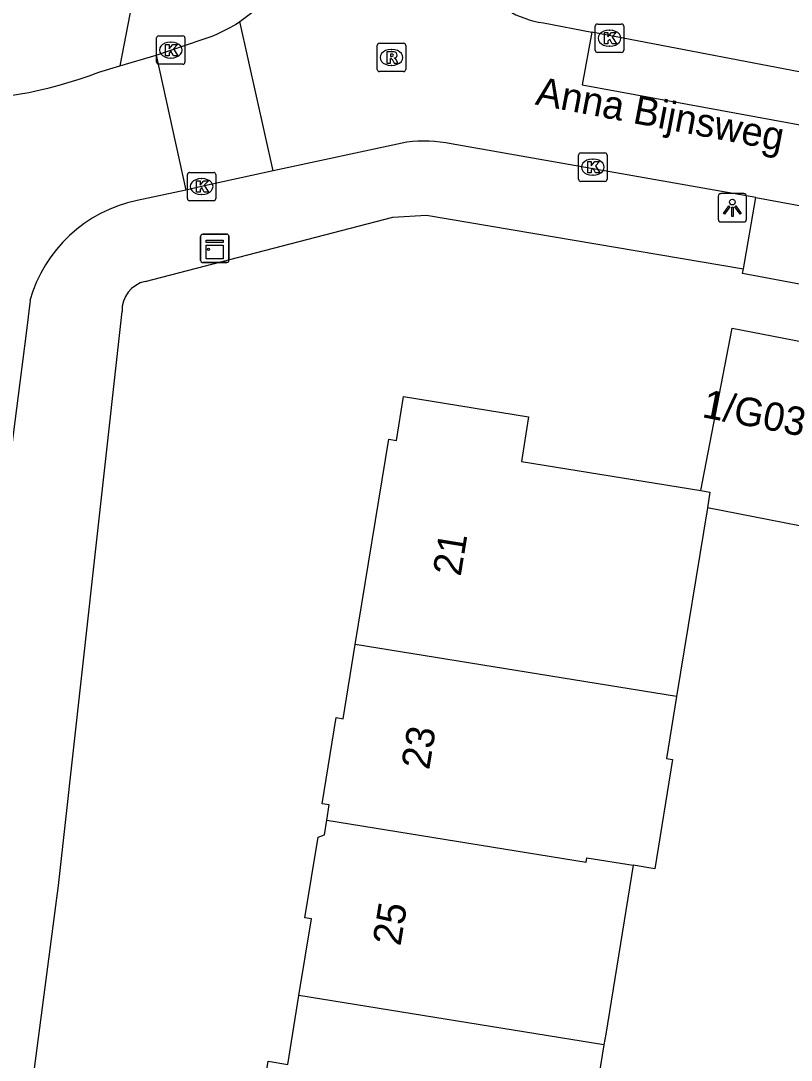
# Model space of a CAD drawing. Extents: x 161402 to 161933, y 381650 to 382313.
# Drawn here: x 161806.73 to 161833.87, y 381916.01 to 381952.64 of the extents above; entities that cross this region are included whole.
import ezdxf

# ---------------------------------------------------------------- set-up
doc = ezdxf.new("R2010")
doc.units = 0
for name, color, linetype in [('IMGEO_Kast', 7, 'Continuous'), ('IMGEO_Kolk', 7, 'Continuous'), ('IMGEO_Lichtpunt', 7, 'Continuous'), ('IMGEO_Openbare_ruimte_label', 7, 'Continuous'), ('IMGEO_Pand', 7, 'Continuous'), ('IMGEO_Pand_nummerreeks', 7, 'Continuous'), ('IMGEO_Rijbaan_lokaal_open', 7, 'Continuous'), ('IMGEO_Rioolput', 7, 'Continuous'), ('IMGEO_Voetpad_open', 7, 'Continuous')]:
    doc.layers.add(name, color=color, linetype=linetype)

msp = doc.modelspace()

# ---------------------------------------------------------------- linework, layer by layer
at = {"layer": 'IMGEO_Kast'}
for p, q in [((161813.066, 381944.199), (161813.066, 381945.04)), ((161813.066, 381945.04), (161813.066, 381944.199)), ((161813.141, 381945.124), (161813.982, 381945.124)), ((161813.982, 381945.124), (161813.141, 381945.124)), ((161814.066, 381945.049), (161814.066, 381944.208)), ((161814.066, 381944.208), (161814.066, 381945.049)), ((161813.991, 381944.124), (161813.15, 381944.124)), ((161813.15, 381944.124), (161813.991, 381944.124))]:
    msp.add_line(p, q, dxfattribs=at)
for points in [[(161813.261, 381944.914), (161813.861, 381944.914), (161813.861, 381944.829), (161813.261, 381944.829), (161813.261, 381944.914)], [(161813.261, 381944.739), (161813.861, 381944.739), (161813.861, 381944.25), (161813.261, 381944.25), (161813.261, 381944.739)]]:
    msp.add_lwpolyline(points, dxfattribs=at)
msp.add_circle((161813.345, 381944.588), 0.0377, dxfattribs=at)
for centre, start, end in [((161813.144, 381945.046), 92.4484, 184.2845), ((161813.144, 381945.046), 92.4484, 184.2845), ((161813.988, 381945.046), 2.4484, 94.2845), ((161813.988, 381945.046), 2.4484, 94.2845), ((161813.144, 381944.202), 182.4484, 274.2845), ((161813.144, 381944.202), 182.4484, 274.2845), ((161813.988, 381944.202), 272.4484, 4.2845), ((161813.988, 381944.202), 272.4484, 4.2845)]:
    msp.add_arc(centre, 0.0779, start, end, dxfattribs=at)
at = {"layer": 'IMGEO_Kolk'}
for p, q in [((161826.973, 381951.603), (161826.973, 381952.455)), ((161827.048, 381952.529), (161827.9, 381952.529)), ((161827.974, 381952.455), (161827.974, 381951.603)), ((161811.516, 381951.184), (161811.516, 381952.036)), ((161811.591, 381952.11), (161812.443, 381952.11)), ((161812.517, 381952.036), (161812.517, 381951.184)), ((161827.461, 381952.309), (161827.486, 381952.309)), ((161812.004, 381951.89), (161812.029, 381951.89)), ((161827.484, 381951.749), (161827.459, 381951.749)), ((161812.027, 381951.33), (161812.002, 381951.33)), ((161827.9, 381951.529), (161827.048, 381951.529)), ((161812.443, 381951.11), (161811.591, 381951.11)), ((161826.459, 381947.984), (161827.311, 381947.984)), ((161826.384, 381947.058), (161826.384, 381947.91)), ((161826.872, 381947.764), (161826.897, 381947.764)), ((161827.385, 381947.91), (161827.385, 381947.058)), ((161812.678, 381947.3), (161813.53, 381947.3)), ((161812.603, 381946.374), (161812.603, 381947.226)), ((161813.091, 381947.08), (161813.116, 381947.08)), ((161813.604, 381947.226), (161813.604, 381946.374)), ((161827.311, 381946.984), (161826.459, 381946.984)), ((161826.895, 381947.204), (161826.87, 381947.204)), ((161813.114, 381946.52), (161813.089, 381946.52)), ((161813.53, 381946.3), (161812.678, 381946.3))]:
    msp.add_line(p, q, dxfattribs=at)
for points in [[(161826.973, 381951.603), (161826.973, 381952.455)], [(161827.048, 381952.529), (161827.9, 381952.529)], [(161827.974, 381952.455), (161827.974, 381951.603)], [(161811.516, 381951.184), (161811.516, 381952.036)], [(161811.591, 381952.11), (161812.443, 381952.11)], [(161812.517, 381952.036), (161812.517, 381951.184)], [(161827.294, 381952.229), (161827.417, 381952.229), (161827.417, 381952.078), (161827.547, 381952.229), (161827.711, 381952.229), (161827.565, 381952.078), (161827.718, 381951.829), (161827.566, 381951.829), (161827.481, 381951.993), (161827.417, 381951.926), (161827.417, 381951.829), (161827.294, 381951.829), (161827.294, 381952.229)], [(161811.837, 381951.81), (161811.96, 381951.81), (161811.96, 381951.659), (161812.09, 381951.81), (161812.254, 381951.81), (161812.108, 381951.659), (161812.261, 381951.41), (161812.109, 381951.41), (161812.024, 381951.574), (161811.96, 381951.507), (161811.96, 381951.41), (161811.837, 381951.41), (161811.837, 381951.81)], [(161827.9, 381951.529), (161827.048, 381951.529)], [(161812.443, 381951.11), (161811.591, 381951.11)], [(161826.459, 381947.984), (161827.311, 381947.984)], [(161826.384, 381947.058), (161826.384, 381947.91)], [(161826.705, 381947.684), (161826.828, 381947.684), (161826.828, 381947.533), (161826.958, 381947.684), (161827.122, 381947.684), (161826.976, 381947.533), (161827.129, 381947.284), (161826.977, 381947.284), (161826.892, 381947.448), (161826.828, 381947.381), (161826.828, 381947.284), (161826.705, 381947.284), (161826.705, 381947.684)], [(161827.385, 381947.91), (161827.385, 381947.058)], [(161812.678, 381947.3), (161813.53, 381947.3)], [(161812.603, 381946.374), (161812.603, 381947.226)], [(161812.924, 381947), (161813.047, 381947), (161813.047, 381946.849), (161813.177, 381947), (161813.341, 381947), (161813.195, 381946.849), (161813.348, 381946.6), (161813.196, 381946.6), (161813.111, 381946.764), (161813.047, 381946.697), (161813.047, 381946.6), (161812.924, 381946.6), (161812.924, 381947)], [(161813.604, 381947.226), (161813.604, 381946.374)], [(161827.311, 381946.984), (161826.459, 381946.984)], [(161813.53, 381946.3), (161812.678, 381946.3)]]:
    msp.add_lwpolyline(points, dxfattribs=at)
for centre, start, end in [((161827.05, 381952.453), 91.552, 178.448), ((161827.05, 381952.453), 91.552, 178.448), ((161827.898, 381952.453), 1.552, 88.448), ((161827.898, 381952.453), 1.552, 88.448), ((161811.593, 381952.034), 91.552, 178.448), ((161811.593, 381952.034), 91.552, 178.448), ((161812.441, 381952.034), 1.552, 88.448), ((161812.441, 381952.034), 1.552, 88.448), ((161827.05, 381951.605), 181.552, 268.448), ((161827.05, 381951.605), 181.552, 268.448), ((161827.898, 381951.605), 271.552, 358.448), ((161827.898, 381951.605), 271.552, 358.448), ((161811.593, 381951.186), 181.552, 268.448), ((161811.593, 381951.186), 181.552, 268.448), ((161812.441, 381951.186), 271.552, 358.448), ((161812.441, 381951.186), 271.552, 358.448), ((161826.461, 381947.908), 91.552, 178.448), ((161826.461, 381947.908), 91.552, 178.448), ((161827.309, 381947.908), 1.552, 88.448), ((161827.309, 381947.908), 1.552, 88.448), ((161812.68, 381947.224), 91.552, 178.448), ((161812.68, 381947.224), 91.552, 178.448), ((161813.528, 381947.224), 1.552, 88.448), ((161813.528, 381947.224), 1.552, 88.448), ((161826.461, 381947.06), 181.552, 268.448), ((161826.461, 381947.06), 181.552, 268.448), ((161827.309, 381947.06), 271.552, 358.448), ((161827.309, 381947.06), 271.552, 358.448), ((161812.68, 381946.376), 181.552, 268.448), ((161812.68, 381946.376), 181.552, 268.448), ((161813.528, 381946.376), 271.552, 358.448), ((161813.528, 381946.376), 271.552, 358.448)]:
    msp.add_arc(centre, 0.0765, start, end, dxfattribs=at)
for centre, major_axis, ratio, start_param, end_param in [((161827.46, 381952.029), (-0.387, 0.002), 0.722429, 4.712389, 7.853982), ((161827.485, 381952.029), (-0.39, 0.002), 0.717154, 1.570796, 4.712389), ((161812.003, 381951.61), (-0.387, 0.002), 0.722429, 4.712389, 7.853982), ((161812.028, 381951.61), (-0.39, 0.002), 0.717154, 1.570796, 4.712389), ((161826.871, 381947.484), (-0.387, 0.002), 0.722429, 4.712389, 7.853982), ((161826.896, 381947.484), (-0.39, 0.002), 0.717154, 1.570796, 4.712389), ((161813.09, 381946.8), (-0.387, 0.002), 0.722429, 4.712389, 7.853982), ((161813.115, 381946.8), (-0.39, 0.002), 0.717154, 1.570796, 4.712389)]:
    msp.add_ellipse(centre, major_axis=major_axis, ratio=ratio, start_param=start_param, end_param=end_param, dxfattribs=at)
at = {"layer": 'IMGEO_Lichtpunt'}
for p, q in [((161832.205, 381946.55), (161831.397, 381946.55)), ((161832.205, 381946.55), (161831.397, 381946.55)), ((161831.303, 381946.455), (161831.303, 381945.648)), ((161831.303, 381946.455), (161831.303, 381945.648)), ((161832.299, 381945.648), (161832.299, 381946.455)), ((161832.299, 381945.648), (161832.299, 381946.455)), ((161831.397, 381945.554), (161832.205, 381945.554)), ((161831.397, 381945.554), (161832.205, 381945.554))]:
    msp.add_line(p, q, dxfattribs=at)
for points in [[(161831.677, 381946.119), (161831.716, 381946.091), (161831.528, 381945.829), (161831.49, 381945.856), (161831.677, 381946.119)], [(161831.779, 381946.071), (161831.826, 381946.071), (161831.826, 381945.749), (161831.779, 381945.749), (161831.779, 381946.071)], [(161831.889, 381946.091), (161831.927, 381946.118), (161832.114, 381945.856), (161832.075, 381945.828), (161831.889, 381946.091)]]:
    msp.add_lwpolyline(points, dxfattribs=at)
msp.add_circle((161831.802, 381946.253), 0.0994, dxfattribs=at)
for centre, start, end in [((161831.397, 381946.455), 90, 180), ((161831.397, 381946.455), 90, 180), ((161832.205, 381946.455), 0, 90), ((161832.205, 381946.455), 0, 90), ((161831.397, 381945.648), 180, 270), ((161831.397, 381945.648), 180, 270), ((161832.205, 381945.648), 270, 0), ((161832.205, 381945.648), 270, 360)]:
    msp.add_arc(centre, 0.0946, start, end, dxfattribs=at)
at = {"layer": 'IMGEO_Pand'}
for points in [[(161830.688, 381936.089), (161831.792, 381941.81), (161835.381, 381941.117)], [(161818.518, 381930.668), (161819.696, 381937.9), (161819.967, 381937.856), (161820.218, 381939.401), (161824.623, 381938.684), (161824.368, 381937.114), (161830.688, 381936.089)], [(161830.688, 381936.089), (161831.012, 381936.036), (161830.921, 381935.476)], [(161830.921, 381935.476), (161829.838, 381928.829)], [(161834.172, 381934.848), (161830.921, 381935.476)], [(161817.512, 381924.476), (161817.599, 381925.01), (161817.348, 381925.05), (161817.842, 381928.084), (161818.091, 381928.043), (161818.518, 381930.668)], [(161829.838, 381928.829), (161818.518, 381930.668)], [(161829.838, 381928.829), (161829.481, 381926.639), (161829.693, 381926.605), (161829.066, 381922.76), (161828.31, 381922.883)], [(161816.533, 381918.296), (161816.972, 381920.99), (161816.741, 381921.028), (161817.204, 381923.872), (161817.428, 381923.957), (161817.512, 381924.476)], [(161817.512, 381924.476), (161826.654, 381922.991), (161826.68, 381923.148), (161828.31, 381922.883)], [(161828.31, 381922.883), (161827.341, 381916.933), (161827.279, 381916.551)], [(161814.828, 381912.15), (161815.451, 381915.973), (161816.136, 381915.861), (161816.533, 381918.296)], [(161827.279, 381916.551), (161816.533, 381918.296)], [(161827.279, 381916.551), (161826.26, 381910.293), (161824.053, 381910.652)]]:
    msp.add_lwpolyline(points, dxfattribs=at)
at = {"layer": 'IMGEO_Rijbaan_lokaal_open'}
for points in [[(161815.628, 381947.352), (161814.45, 381952.615)], [(161825.144, 381952.573), (161826.853, 381952.245)], [(161826.853, 381952.245), (161826.511, 381950.381), (161841.229, 381947.681)], [(161811.499, 381951.427), (161812.017, 381951.61), (161813.12, 381951.985)], [(161810.228, 381951.049), (161811.499, 381951.427)], [(161811.499, 381951.427), (161812.553, 381946.677)], [(161809.488, 381950.828), (161810.228, 381951.049)], [(161820.334, 381948.364), (161815.628, 381947.352)], [(161832.624, 381946.415), (161821.896, 381948.301)], [(161815.628, 381947.352), (161813.104, 381946.8), (161812.553, 381946.677)], [(161812.553, 381946.677), (161810.83, 381946.306)], [(161832.624, 381946.415), (161840.719, 381944.921)], [(161807.058, 381942.789), (161806.923, 381941.638), (161805.889, 381933.665), (161804.496, 381922.134), (161803.877, 381917.126)]]:
    msp.add_lwpolyline(points, dxfattribs=at)
for centre, radius, start, end in [((161810.822, 381957.769), 6.303, 305.142, 347.5685), ((161825.556, 381955.744), 3.198, 166.2409, 262.5929), ((161811.723, 381956.654), 4.873, 286.6617, 304.0306), ((161803.949, 381965.532), 15.713, 247.8699, 290.64), ((161820.924, 381943.604), 4.796, 78.3111, 97.0695), ((161811.844, 381941.437), 4.974, 101.7679, 164.2249)]:
    msp.add_arc(centre, radius, start, end, dxfattribs=at)
at = {"layer": 'IMGEO_Rioolput'}
for p, q in [((161819.292, 381950.925), (161819.292, 381951.777)), ((161819.367, 381951.851), (161820.219, 381951.851)), ((161819.78, 381951.631), (161819.805, 381951.631)), ((161820.293, 381951.777), (161820.293, 381950.925)), ((161819.803, 381951.071), (161819.778, 381951.071)), ((161820.219, 381950.851), (161819.367, 381950.851))]:
    msp.add_line(p, q, dxfattribs=at)
for points in [[(161819.292, 381950.925), (161819.292, 381951.777)], [(161819.367, 381951.851), (161820.219, 381951.851)], [(161820.293, 381951.777), (161820.293, 381950.925)], [(161819.881, 381951.549), (161819.629, 381951.551), (161819.629, 381951.151)], [(161819.629, 381951.151), (161819.753, 381951.151), (161819.753, 381951.313), (161819.764, 381951.313)], [(161819.807, 381951.47), (161819.753, 381951.47), (161819.753, 381951.389)], [(161819.753, 381951.389), (161819.805, 381951.389)], [(161819.811, 381951.284), (161819.882, 381951.151), (161820.022, 381951.151), (161819.957, 381951.277)], [(161820.219, 381950.851), (161819.367, 381950.851)]]:
    msp.add_lwpolyline(points, dxfattribs=at)
for centre, radius, start, end in [((161819.369, 381951.775), 0.0765, 91.552, 178.448), ((161819.369, 381951.775), 0.0765, 91.552, 178.448), ((161820.217, 381951.775), 0.0765, 1.552, 88.448), ((161820.217, 381951.775), 0.0765, 1.552, 88.448), ((161819.763, 381951.26), 0.0533, 26.0293, 88.6989), ((161819.789, 381951.578), 0.19, 274.7715, 282.9687), ((161819.813, 381951.374), 0.0964, 77.0061, 93.1865), ((161819.827, 381951.431), 0.0378, 276.6634, 79.6772), ((161819.88, 381951.439), 0.109, 350.3612, 89.416), ((161819.878, 381951.439), 0.112, 277.5842, 350.9817), ((161819.862, 381951.224), 0.108, 29.5134, 73.7905), ((161819.369, 381950.927), 0.0765, 181.552, 268.448), ((161819.369, 381950.927), 0.0765, 181.552, 268.448), ((161820.217, 381950.927), 0.0765, 271.552, 358.448), ((161820.217, 381950.927), 0.0765, 271.552, 358.448)]:
    msp.add_arc(centre, radius, start, end, dxfattribs=at)
for centre, major_axis, ratio, start_param, end_param in [((161819.779, 381951.351), (-0.387, 0.002), 0.722429, 4.712389, 7.853982), ((161819.804, 381951.351), (-0.39, 0.002), 0.717154, 1.570796, 4.712389)]:
    msp.add_ellipse(centre, major_axis=major_axis, ratio=ratio, start_param=start_param, end_param=end_param, dxfattribs=at)
at = {"layer": 'IMGEO_Voetpad_open'}
for points in [[(161784.276, 381957.939), (161785.503, 381960.377), (161795.166, 381958.474), (161794.855, 381956.97), (161793.688, 381954.764), (161795.715, 381953.673), (161796.806, 381955.759), (161796.395, 381956.022), (161796.644, 381956.673), (161796.895, 381958.043), (161811.053, 381955.38), (161810.228, 381951.049)], [(161841.561, 381949.474), (161835.816, 381950.524), (161826.853, 381952.245)], [(161832.192, 381943.9), (161832.624, 381946.415)], [(161811.12, 381943.457), (161819.839, 381945.717), (161821.03, 381945.795), (161832.192, 381943.9)], [(161842.874, 381941.733), (161832.159, 381943.741), (161832.192, 381943.9)], [(161778.698, 381768.78), (161781.039, 381777.203), (161788.629, 381808.145), (161791.311, 381819.878), (161794.918, 381837.231), (161795.748, 381841.221), (161796.717, 381845.885), (161801.214, 381871.562), (161802.683, 381881.227), (161808.066, 381922.168), (161810.3, 381942.403)]]:
    msp.add_lwpolyline(points, dxfattribs=at)
msp.add_arc((161811.338, 381942.441), 1.039, 102.1162, 182.1187, dxfattribs=at)

# ---------------------------------------------------------------- texts
at = {"layer": 'IMGEO_Openbare_ruimte_label'}
msp.add_text('Anna Bijnsweg', height=1, rotation=349.2184, dxfattribs=at).set_placement((161824.828, 381949.697))
at = {"layer": 'IMGEO_Pand_nummerreeks'}
for s, rotation, p in [('1/G03', 349.0706, (161830.699, 381938.68)), ('21', 80.7518, (161822.228, 381933.039)), ('23', 80.7584, (161821.118, 381926.22)), ('25', 80.7584, (161820.107, 381920.011))]:
    msp.add_text(s, height=1, rotation=rotation, dxfattribs=at).set_placement(p)

doc.saveas('drawing.dxf')
